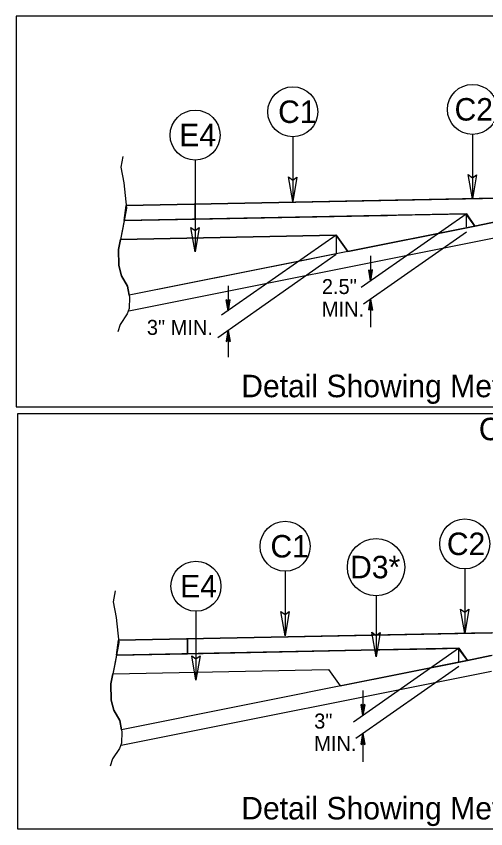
# Model space of a CAD drawing. Extents: x 18938 to 19565, y 6931 to 7973.
# Drawn here: x 19418.7 to 19450.1, y 7918.3 to 7972.5 of the extents above; entities that cross this region are included whole.
import ezdxf

# ---------------------------------------------------------------- set-up
doc = ezdxf.new("R2010")
doc.units = 0
for name, color, linetype in [('Old_Level_11', 7, 'Continuous'), ('Old_Level_2', 7, 'Continuous'), ('Prop Terminator CELL', 7, 'Continuous'), ('Sheet Block Title CELL', 7, 'Continuous'), ('Typical Hinge Slope Arterial CELL', 7, 'Continuous'), ('Typical ID Circle CELL', 7, 'Continuous'), ('Typical Terminator CELL', 7, 'Continuous'), ('Typical Text General CELL', 7, 'Continuous'), ('Typical Text Label CELL', 7, 'Continuous')]:
    doc.layers.add(name, color=color, linetype=linetype)

# ---------------------------------------------------------------- blocks, each defined once
blk = doc.blocks.new('TERMINATOR')
at = {"layer": 'Typical Text General CELL'}
blk.add_lwpolyline([(-0.469, 0.081), (0, 0), (-0.471, -0.083), (-0.411, 0)], close=True, dxfattribs=at)

msp = doc.modelspace()

# ---------------------------------------------------------------- linework, layer by layer
at = {"layer": 'Old_Level_2'}
for points in [[(19418.742, 7946.472), (19482.355, 7946.472), (19482.355, 7972.544), (19418.742, 7972.544)], [(19418.832, 7918.315), (19482.444, 7918.315), (19482.444, 7946.011), (19418.832, 7946.011)]]:
    msp.add_lwpolyline(points, close=True, dxfattribs=at)
at = {"layer": 'Sheet Block Title CELL'}
for p, q in [((19448.762, 7959.344), (19425.941, 7958.906)), ((19448.762, 7959.344), (19448.762, 7959.344)), ((19449.35, 7958.542), (19448.762, 7959.344)), ((19425.941, 7958.906), (19425.699, 7957.652)), ((19425.941, 7958.906), (19425.941, 7958.906)), ((19440.866, 7956.843), (19449.35, 7958.542)), ((19425.699, 7957.652), (19440.086, 7957.94)), ((19440.086, 7957.94), (19440.866, 7956.843)), ((19425.432, 7929.906), (19425.189, 7928.652)), ((19448.253, 7930.344), (19425.432, 7929.906)), ((19425.432, 7929.906), (19425.432, 7929.906)), ((19448.253, 7930.344), (19448.253, 7930.344)), ((19448.84, 7929.543), (19448.253, 7930.344)), ((19440.357, 7927.843), (19448.84, 7929.543)), ((19425.189, 7928.652), (19439.576, 7928.94)), ((19439.576, 7928.94), (19440.357, 7927.843))]:
    msp.add_line(p, q, dxfattribs=at)
at = {"layer": 'Typical Hinge Slope Arterial CELL'}
for p, q in [((19449.619, 7960.376), (19430.676, 7959.997)), ((19449.623, 7960.351), (19449.619, 7960.376)), ((19449.627, 7960.376), (19449.623, 7960.351)), ((19450.974, 7960.403), (19449.627, 7960.376)), ((19426.083, 7959.906), (19426.08, 7959.883)), ((19430.676, 7959.997), (19426.083, 7959.906)), ((19430.676, 7959.997), (19430.676, 7959)), ((19430.676, 7959), (19430.676, 7959.997)), ((19443.504, 7959.256), (19443.504, 7959.257)), ((19448.791, 7959.362), (19449.35, 7958.542)), ((19425.941, 7958.906), (19430.676, 7959)), ((19425.945, 7958.932), (19425.941, 7958.906)), ((19449.35, 7958.542), (19450.937, 7958.873)), ((19430.165, 7930.996), (19425.572, 7930.904)), ((19449.108, 7931.374), (19430.165, 7930.996)), ((19430.165, 7930.996), (19430.165, 7929.999)), ((19430.165, 7929.999), (19430.165, 7930.996)), ((19449.112, 7931.35), (19449.108, 7931.374)), ((19449.117, 7931.374), (19449.112, 7931.35)), ((19450.463, 7931.401), (19449.117, 7931.374)), ((19425.572, 7930.904), (19425.569, 7930.881)), ((19425.431, 7929.904), (19430.165, 7929.999)), ((19425.434, 7929.93), (19425.431, 7929.904)), ((19442.993, 7930.255), (19442.993, 7930.255)), ((19448.28, 7930.361), (19448.839, 7929.541)), ((19448.839, 7929.541), (19450.426, 7929.871))]:
    msp.add_line(p, q, dxfattribs=at)
for points in [[(19426.08, 7959.883), (19426.094, 7959.746), (19425.945, 7958.932)], [(19430.676, 7959), (19442.263, 7959.232), (19443.504, 7959.256)], [(19443.504, 7959.256), (19444.734, 7959.281), (19447.216, 7959.331), (19448.791, 7959.362)], [(19443.504, 7959.257), (19443.504, 7959.256)], [(19425.569, 7930.881), (19425.583, 7930.745), (19425.434, 7929.93)], [(19430.165, 7929.999), (19441.752, 7930.23), (19442.993, 7930.255)], [(19442.993, 7930.255), (19444.223, 7930.28), (19446.705, 7930.329), (19448.28, 7930.361)], [(19442.993, 7930.255), (19442.993, 7930.255)]]:
    msp.add_lwpolyline(points, dxfattribs=at)
at = {"layer": 'Typical ID Circle CELL'}
for p, q in [((19450.974, 7960.403), (19426.083, 7959.906)), ((19426.083, 7959.906), (19450.974, 7960.403)), ((19425.941, 7958.906), (19426.083, 7959.906)), ((19448.791, 7959.362), (19425.941, 7958.906)), ((19448.791, 7959.362), (19425.941, 7958.906)), ((19448.762, 7959.344), (19441.749, 7954.432)), ((19448.759, 7959.353), (19448.759, 7958.486)), ((19449.35, 7958.542), (19448.791, 7959.362)), ((19448.791, 7959.336), (19449.35, 7958.542)), ((19451.011, 7958.873), (19426.27, 7953.923)), ((19450.937, 7958.873), (19449.35, 7958.542)), ((19448.779, 7958.143), (19441.916, 7953.338)), ((19440.086, 7957.94), (19425.699, 7957.652)), ((19425.699, 7957.652), (19440.086, 7957.94)), ((19450.965, 7957.807), (19426.262, 7952.866)), ((19440.086, 7957.94), (19432.447, 7952.591)), ((19440.868, 7956.84), (19440.086, 7957.94)), ((19440.086, 7957.94), (19440.086, 7956.685)), ((19440.086, 7957.94), (19440.866, 7956.843)), ((19440.079, 7956.645), (19432.182, 7951.088)), ((19440.866, 7956.843), (19437.58, 7956.185)), ((19440.866, 7956.843), (19440.086, 7956.686)), ((19442.388, 7956.548), (19442.388, 7954.88)), ((19437.58, 7956.185), (19426.27, 7953.923)), ((19442.388, 7954.88), (19442.259, 7955.611)), ((19442.388, 7955.516), (19442.259, 7955.611)), ((19442.388, 7954.88), (19442.277, 7955.598)), ((19442.295, 7955.584), (19442.388, 7954.88)), ((19442.388, 7954.88), (19442.314, 7955.571)), ((19442.333, 7955.557), (19442.388, 7954.88)), ((19442.388, 7954.88), (19442.351, 7955.544)), ((19442.37, 7955.53), (19442.388, 7954.88)), ((19442.388, 7954.88), (19442.518, 7955.611)), ((19442.518, 7955.611), (19442.388, 7955.516)), ((19442.5, 7955.598), (19442.388, 7954.88)), ((19442.388, 7954.88), (19442.479, 7955.584)), ((19442.461, 7955.571), (19442.388, 7954.88)), ((19442.388, 7954.88), (19442.443, 7955.557)), ((19442.424, 7955.544), (19442.388, 7954.88)), ((19442.388, 7954.88), (19442.406, 7955.53)), ((19442.388, 7955.516), (19442.388, 7954.88)), ((19432.877, 7954.554), (19432.877, 7952.891)), ((19432.877, 7952.891), (19432.747, 7953.623)), ((19432.877, 7953.529), (19432.747, 7953.623)), ((19432.877, 7952.891), (19432.765, 7953.61)), ((19432.785, 7953.595), (19432.877, 7952.891)), ((19432.877, 7952.891), (19432.804, 7953.583)), ((19432.822, 7953.57), (19432.877, 7952.891)), ((19432.877, 7952.891), (19432.84, 7953.556)), ((19432.858, 7953.542), (19432.877, 7952.891)), ((19432.877, 7952.891), (19433.006, 7953.623)), ((19433.006, 7953.623), (19432.877, 7953.529)), ((19432.987, 7953.61), (19432.877, 7952.891)), ((19432.877, 7952.891), (19432.969, 7953.595)), ((19432.951, 7953.583), (19432.877, 7952.891)), ((19432.877, 7952.891), (19432.932, 7953.57)), ((19432.914, 7953.556), (19432.877, 7952.891)), ((19432.877, 7952.891), (19432.895, 7953.542)), ((19432.877, 7953.529), (19432.877, 7952.891)), ((19442.388, 7953.669), (19442.259, 7952.937)), ((19442.277, 7952.951), (19442.388, 7953.669)), ((19442.388, 7953.669), (19442.295, 7952.964)), ((19442.314, 7952.979), (19442.388, 7953.669)), ((19442.388, 7953.669), (19442.333, 7952.991)), ((19442.351, 7953.004), (19442.388, 7953.669)), ((19442.388, 7953.669), (19442.37, 7953.018)), ((19442.388, 7953.669), (19442.388, 7951.79)), ((19442.388, 7953.669), (19442.518, 7952.937)), ((19442.388, 7953.032), (19442.388, 7953.669)), ((19442.406, 7953.018), (19442.388, 7953.669)), ((19442.388, 7953.669), (19442.424, 7953.004)), ((19442.443, 7952.991), (19442.388, 7953.669)), ((19442.388, 7953.669), (19442.461, 7952.979)), ((19442.479, 7952.964), (19442.388, 7953.669)), ((19442.388, 7953.669), (19442.5, 7952.951)), ((19442.259, 7952.937), (19442.388, 7953.032)), ((19442.388, 7953.032), (19442.518, 7952.937)), ((19432.877, 7951.575), (19432.747, 7950.843)), ((19432.767, 7950.857), (19432.877, 7951.575)), ((19432.877, 7951.575), (19432.785, 7950.87)), ((19432.804, 7950.884), (19432.877, 7951.575)), ((19432.877, 7951.575), (19432.822, 7950.898)), ((19432.84, 7950.911), (19432.877, 7951.575)), ((19432.877, 7951.575), (19432.858, 7950.923)), ((19432.877, 7951.575), (19432.877, 7949.796)), ((19432.877, 7951.575), (19433.006, 7950.843)), ((19432.877, 7950.938), (19432.877, 7951.575)), ((19432.895, 7950.923), (19432.877, 7951.575)), ((19432.877, 7951.575), (19432.914, 7950.911)), ((19432.933, 7950.898), (19432.877, 7951.575)), ((19432.877, 7951.575), (19432.951, 7950.884)), ((19432.969, 7950.87), (19432.877, 7951.575)), ((19432.877, 7951.575), (19432.987, 7950.857)), ((19432.747, 7950.843), (19432.877, 7950.938)), ((19432.877, 7950.938), (19433.006, 7950.843)), ((19450.463, 7931.401), (19425.572, 7930.904)), ((19425.572, 7930.904), (19450.463, 7931.401)), ((19425.431, 7929.904), (19425.572, 7930.904)), ((19448.28, 7930.361), (19425.431, 7929.904)), ((19448.28, 7930.361), (19425.431, 7929.904)), ((19448.251, 7930.342), (19441.238, 7925.43)), ((19448.248, 7930.352), (19448.248, 7929.484)), ((19448.839, 7929.541), (19448.28, 7930.361)), ((19448.28, 7930.334), (19448.839, 7929.541)), ((19450.501, 7929.871), (19425.759, 7924.922)), ((19450.426, 7929.871), (19448.839, 7929.541)), ((19448.268, 7929.142), (19441.405, 7924.337)), ((19450.454, 7928.806), (19425.751, 7923.865)), ((19441.877, 7927.547), (19441.877, 7925.879)), ((19441.877, 7925.879), (19441.748, 7926.61)), ((19441.877, 7926.515), (19441.748, 7926.61)), ((19441.877, 7925.879), (19441.766, 7926.596)), ((19441.785, 7926.582), (19441.877, 7925.879)), ((19441.877, 7925.879), (19441.803, 7926.57)), ((19441.822, 7926.556), (19441.877, 7925.879)), ((19441.877, 7925.879), (19441.84, 7926.542)), ((19441.859, 7926.528), (19441.877, 7925.879)), ((19441.877, 7925.879), (19442.007, 7926.61)), ((19442.007, 7926.61), (19441.877, 7926.515)), ((19441.989, 7926.596), (19441.877, 7925.879)), ((19441.877, 7925.879), (19441.969, 7926.582)), ((19441.95, 7926.57), (19441.877, 7925.879)), ((19441.877, 7925.879), (19441.932, 7926.556)), ((19441.914, 7926.542), (19441.877, 7925.879)), ((19441.877, 7925.879), (19441.895, 7926.528)), ((19441.877, 7926.515), (19441.877, 7925.879)), ((19441.877, 7924.667), (19441.748, 7923.935)), ((19441.766, 7923.95), (19441.877, 7924.667)), ((19441.877, 7924.667), (19441.785, 7923.963)), ((19441.803, 7923.977), (19441.877, 7924.667)), ((19441.877, 7924.667), (19441.822, 7923.99)), ((19441.84, 7924.003), (19441.877, 7924.667)), ((19441.877, 7924.667), (19441.859, 7924.017)), ((19441.877, 7924.667), (19441.877, 7922.789)), ((19441.877, 7924.667), (19442.007, 7923.935)), ((19441.877, 7924.03), (19441.877, 7924.667)), ((19441.895, 7924.017), (19441.877, 7924.667)), ((19441.877, 7924.667), (19441.914, 7924.003)), ((19441.932, 7923.99), (19441.877, 7924.667)), ((19441.877, 7924.667), (19441.95, 7923.977)), ((19441.969, 7923.963), (19441.877, 7924.667)), ((19441.877, 7924.667), (19441.989, 7923.95)), ((19441.748, 7923.935), (19441.877, 7924.03)), ((19441.877, 7924.03), (19442.007, 7923.935))]:
    msp.add_line(p, q, dxfattribs=at)
for points in [[(19425.852, 7963.191), (19425.719, 7962.461), (19425.919, 7961.425), (19426.094, 7959.746), (19425.852, 7958.421), (19425.565, 7956.987), (19425.587, 7955.904), (19425.764, 7955.221), (19426.162, 7954.535), (19426.294, 7953.785), (19426.272, 7953.034), (19426.139, 7952.68), (19425.676, 7951.974), (19425.521, 7951.488)], [(19426.083, 7959.906), (19450.974, 7960.403), (19475.866, 7959.906)], [(19426.269, 7953.923), (19426.162, 7954.535), (19425.764, 7955.221), (19425.587, 7955.904), (19425.565, 7956.987), (19425.698, 7957.652)], [(19425.341, 7934.189), (19425.208, 7933.46), (19425.408, 7932.423), (19425.583, 7930.745), (19425.341, 7929.42), (19425.055, 7927.985), (19425.076, 7926.903), (19425.253, 7926.219), (19425.651, 7925.534), (19425.783, 7924.783), (19425.761, 7924.033), (19425.628, 7923.679), (19425.165, 7922.972), (19425.011, 7922.487)], [(19475.355, 7930.904), (19450.464, 7931.401), (19425.572, 7930.904)], [(19425.758, 7924.922), (19425.651, 7925.534), (19425.253, 7926.219), (19425.076, 7926.903), (19425.055, 7927.985), (19425.187, 7928.65)]]:
    msp.add_lwpolyline(points, dxfattribs=at)
at = {"layer": 'Typical Terminator CELL'}
for p, q in [((19449.181, 7964.661), (19449.181, 7960.351)), ((19437.192, 7964.501), (19437.192, 7960.191)), ((19430.676, 7962.949), (19430.676, 7956.82)), ((19436.681, 7935.5), (19436.681, 7931.19)), ((19448.67, 7935.66), (19448.67, 7931.35)), ((19442.748, 7933.864), (19442.748, 7929.8)), ((19430.733, 7932.836), (19430.733, 7928.228))]:
    msp.add_line(p, q, dxfattribs=at)
for centre, radius in [((19449.181, 7966.329), 1.668), ((19437.193, 7966.169), 1.668), ((19430.675, 7964.616), 1.668), ((19436.682, 7937.167), 1.668), ((19448.67, 7937.327), 1.668), ((19442.748, 7935.777), 1.913), ((19430.733, 7934.504), 1.668)]:
    msp.add_circle(centre, radius, dxfattribs=at)

# ---------------------------------------------------------------- block references
at = {"layer": 'Typical Text General CELL', "xscale": 3.45, "yscale": 3.45, "rotation": -90.00000000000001}
for p in [(19449.181, 7960.351), (19449.181, 7960.351), (19437.192, 7960.191), (19437.192, 7960.191), (19430.676, 7956.82), (19430.676, 7956.82), (19436.681, 7931.19), (19436.681, 7931.19), (19448.67, 7931.35), (19448.67, 7931.35), (19442.748, 7929.8), (19442.748, 7929.8), (19430.733, 7928.228)]:
    msp.add_blockref('TERMINATOR', p, dxfattribs=at)

# ---------------------------------------------------------------- texts
at = {"layer": 'Old_Level_11'}
for p in [(19433.756, 7947.116), (19433.756, 7918.938)]:
    msp.add_text('Detail Showing Method of Wedging', height=1.5, rotation=360, dxfattribs=at).set_placement(p)
at = {"layer": 'Prop Terminator CELL'}
for s, p in [('C1', (19436.215, 7965.422)), ('C2', (19447.986, 7965.582)), ('E4', (19429.622, 7963.87)), ('C2', (19447.475, 7936.581)), ('C1', (19435.704, 7936.421)), ('D3*', (19441.018, 7935.031)), ('E4', (19429.679, 7933.757))]:
    msp.add_text(s, height=1.5, rotation=360, dxfattribs=at).set_placement(p)
at = {"layer": 'Typical ID Circle CELL'}
for s, p in [('2.5"', (19439.131, 7954.003)), ('MIN.', (19439.131, 7952.503)), ('3" MIN.', (19427.455, 7951.277)), ('3"', (19438.62, 7925.002)), ('MIN.', (19438.62, 7923.502))]:
    msp.add_text(s, height=1, rotation=360, dxfattribs=at).set_placement(p)
at = {"layer": 'Typical Text Label CELL'}
msp.add_text('C -Y1-, -Y2-, -Y3-, -Y3A-,', height=1.5, dxfattribs=at).set_placement((19449.607, 7944.246))

doc.saveas('drawing.dxf')
